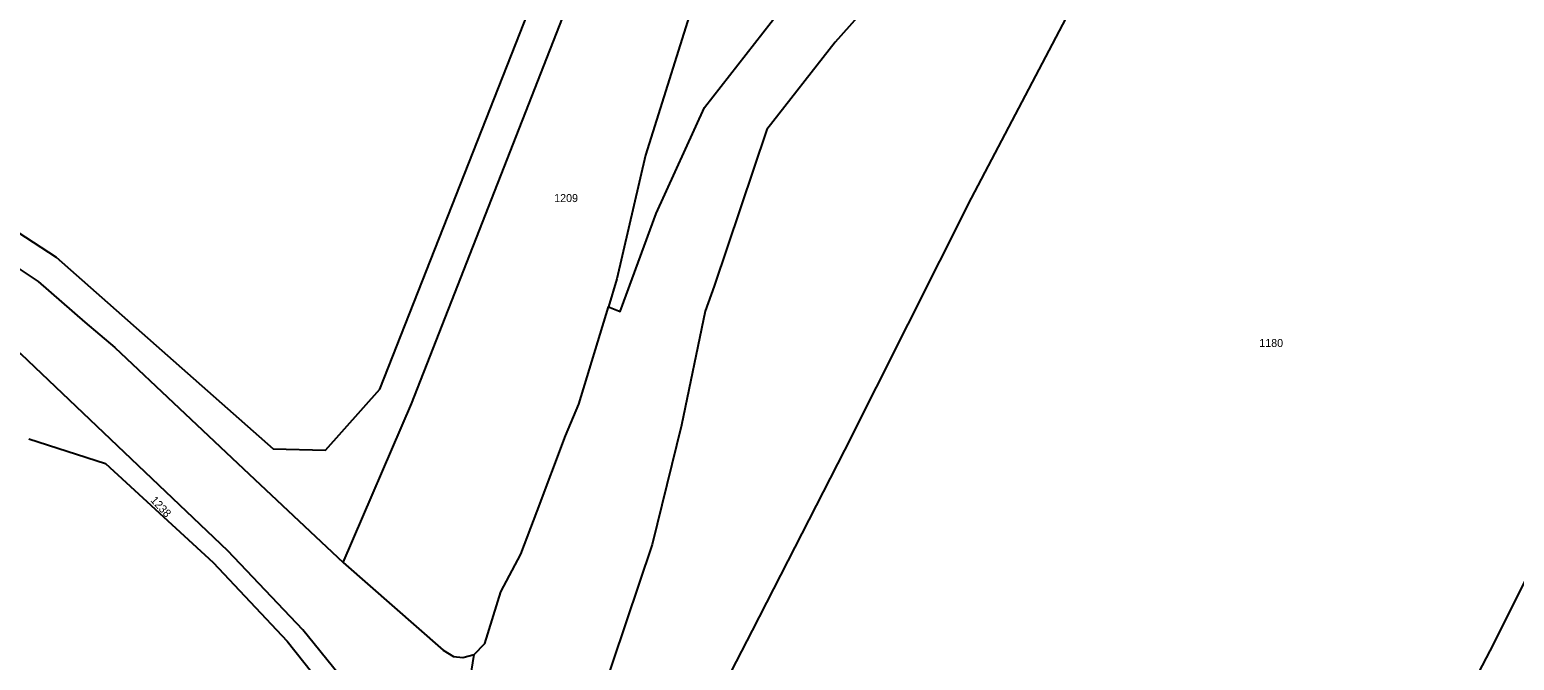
# Model space of a CAD drawing. Extents: x -746176 to -739709, y -1128407 to -1124482.
# Drawn here: x -742787.6 to -742472.1, y -1125750.3 to -1125616.4 of the extents above; entities that cross this region are included whole.
import ezdxf

# ---------------------------------------------------------------- set-up
doc = ezdxf.new("R2010")
doc.units = 0
doc.layers.add('Hranice parcel', color=7, linetype='Continuous')
doc.layers.add('Parcelní čísla', color=7, linetype='Continuous')

msp = doc.modelspace()

# ---------------------------------------------------------------- linework, layer by layer
at = {"layer": 'Hranice parcel'}
msp.add_line((-742697.47, -1125777.04), (-742693.19, -1125749.09), dxfattribs=at)
for points in [[(-742370.36, -1125347.04), (-742432.34, -1125415.1), (-742477.69, -1125464.92), (-742517.45, -1125508.68), (-742552, -1125547.84), (-742583.39, -1125581.95), (-742616.43, -1125619.02), (-742630.96, -1125637.59), (-742642.15, -1125670.87), (-742644.08, -1125676.14), (-742649.1, -1125700.36), (-742655.33, -1125725.7), (-742666.52, -1125758.99), (-742666.57, -1125763.1)], [(-742961.49, -1125589.76), (-742903.5, -1125612.7), (-742805.05, -1125649.66), (-742781.96, -1125664.69), (-742735.85, -1125705.38), (-742724.75, -1125705.66), (-742713.17, -1125692.7), (-742660.04, -1125557.63), (-742636.36, -1125514.75)], [(-742653.4, -1125781.54), (-742634, -1125743.96), (-742614.36, -1125705.64), (-742587.5, -1125652.14), (-742562.32, -1125604.29), (-742540.18, -1125561.73), (-742516.02, -1125518.69), (-742476.97, -1125538.52), (-742438.5, -1125559.02), (-742396.16, -1125584.03)], [(-742720.96, -1125729.52), (-742706.46, -1125695.82), (-742653.41, -1125560.36), (-742620.57, -1125529.11)], [(-742620.57, -1125529.11), (-742645.5, -1125607.15), (-742656.73, -1125643.05), (-742662.84, -1125669.27), (-742664.64, -1125675.21)], [(-743013.26, -1125572.26), (-743015.37, -1125576.06), (-742996.62, -1125585.01), (-742994.55, -1125581.04), (-742956.27, -1125598.27), (-742906.41, -1125617.96), (-742863.3, -1125633.64), (-742807.54, -1125655.45), (-742785.81, -1125669.86), (-742775.87, -1125678.49), (-742769.54, -1125683.84), (-742742.16, -1125709.62), (-742720.96, -1125729.52)], [(-742526.37, -1125842.12), (-742476.44, -1125746.67), (-742414.31, -1125621.99), (-742400.46, -1125594.2), (-742396.16, -1125584.03)], [(-742664.64, -1125675.21), (-742662.12, -1125676.25), (-742654.48, -1125655.41), (-742644.23, -1125632.93), (-742626.51, -1125610.26)], [(-742714.55, -1125762.38), (-742729.59, -1125743.86), (-742745.51, -1125727.03), (-742789.4, -1125685.29), (-742799.96, -1125676.5), (-742797.78, -1125673.65), (-742804.75, -1125668.98), (-742814.6, -1125664.12), (-742816.05, -1125666.93)], [(-742693.19, -1125749.09), (-742690.92, -1125746.74), (-742687.5, -1125735.75), (-742683.25, -1125727.76), (-742679.8, -1125718.6), (-742673.76, -1125702.63), (-742670.9, -1125695.88), (-742664.64, -1125675.21)], [(-742787.81, -1125703.29), (-742771.53, -1125708.51), (-742748.64, -1125729.55), (-742732.87, -1125746.24), (-742716.78, -1125766.45)], [(-742720.96, -1125729.52), (-742699.72, -1125748.18), (-742697.55, -1125749.49), (-742695.54, -1125749.67), (-742693.19, -1125749.09)]]:
    msp.add_lwpolyline(points, dxfattribs=at)

# ---------------------------------------------------------------- texts
at = {"layer": 'Parcelní čísla'}
for s, p in [('1209', (-742676.15, -1125652.99)), ('1180', (-742526.32, -1125683.77))]:
    msp.add_text(s, height=1.7, dxfattribs=at).set_placement(p)
msp.add_text('1238', height=1.7, rotation=313, dxfattribs=at).set_placement((-742762.06, -1125716.41))

doc.saveas('drawing.dxf')
